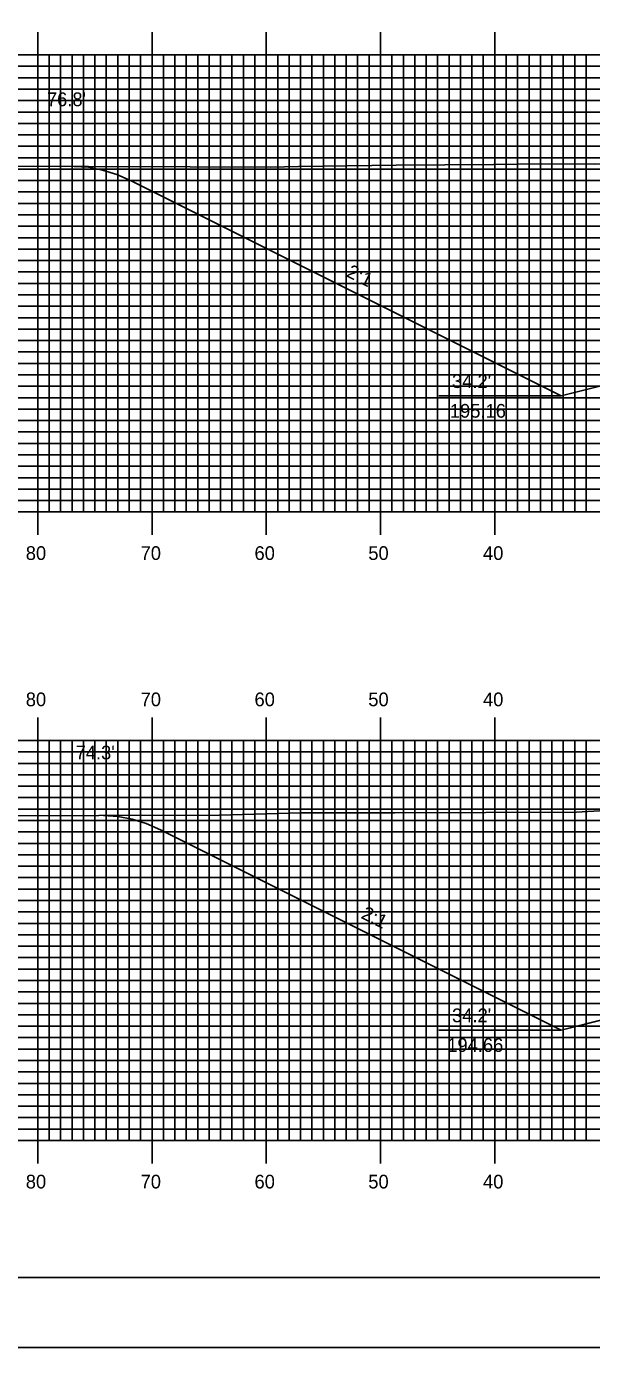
# Model space of a CAD drawing. Extents: x 1800355 to 1800699, y 442591 to 442811.
# Drawn here: x 1800440 to 1800489.5, y 442590.5 to 442706.2 of the extents above; entities that cross this region are included whole.
import ezdxf

# ---------------------------------------------------------------- set-up
doc = ezdxf.new("R2010")
doc.units = 0
for name, color, linetype in [('ANNOTATION', 7, 'Continuous'), ('BORDER', 7, 'Continuous'), ('D_Roadway_Centerline', 7, 'Continuous'), ('D_Roadway_SlopeLines', 7, 'Continuous'), ('D_Text_Standard', 7, 'Continuous'), ('H_V ANNOTATION', 7, 'Continuous'), ('MAJOR', 7, 'Continuous'), ('MINOR', 7, 'Continuous'), ('PDRAIN', 7, 'Continuous'), ('PLOT BOUNDARY', 7, 'Continuous'), ('S_Roadway_Centerline', 7, 'Continuous')]:
    doc.layers.add(name, color=color, linetype=linetype)

msp = doc.modelspace()

# ---------------------------------------------------------------- linework, layer by layer
at = {"layer": 'BORDER'}
msp.add_lwpolyline([(1800371.44, 442596.67), (1800691.44, 442596.67), (1800691.44, 442806.67), (1800371.44, 442806.67)], close=True, dxfattribs=at)
at = {"layer": 'D_Roadway_Centerline'}
msp.add_lwpolyline([(1800446.79, 442637.11), (1800448.04, 442637.03), (1800449.29, 442636.8), (1800450.54, 442636.41), (1800451.79, 442635.86), (1800486.86, 442618.33), (1800490.86, 442619.33), (1800501.04, 442621.87), (1800509.04, 442622.19), (1800521.04, 442621.95), (1800533.04, 442621.71), (1800541.04, 442621.39), (1800551.21, 442618.85), (1800555.21, 442617.85), (1800591.97, 442636.22), (1800593.22, 442636.77), (1800594.47, 442637.16), (1800595.72, 442637.38), (1800596.97, 442637.45)], dxfattribs=at)
at = {"layer": 'D_Roadway_SlopeLines'}
for points in [[(1800486.86, 442673.83), (1800449.22, 442692.65), (1800447.97, 442693.2), (1800446.72, 442693.59), (1800445.47, 442693.83), (1800444.22, 442693.91)], [(1800501.04, 442677.37), (1800486.86, 442673.83)], [(1800486.86, 442618.33), (1800451.79, 442635.86), (1800450.54, 442636.41), (1800449.29, 442636.8), (1800448.04, 442637.03), (1800446.79, 442637.11)], [(1800501.04, 442621.87), (1800486.86, 442618.33)]]:
    msp.add_lwpolyline(points, dxfattribs=at)
at = {"layer": 'MAJOR'}
for p, q in [((1800441.04, 442705.67), (1800441.04, 442703.67)), ((1800451.04, 442705.67), (1800451.04, 442703.67)), ((1800461.04, 442705.67), (1800461.04, 442703.67)), ((1800471.04, 442705.67), (1800471.04, 442703.67)), ((1800481.04, 442705.67), (1800481.04, 442703.67)), ((1800381.04, 442703.67), (1800661.04, 442703.67)), ((1800381.04, 442703.67), (1800661.04, 442703.67)), ((1800441.04, 442663.67), (1800441.04, 442703.67)), ((1800451.04, 442663.67), (1800451.04, 442703.67)), ((1800461.04, 442663.67), (1800461.04, 442703.67)), ((1800471.04, 442663.67), (1800471.04, 442703.67)), ((1800481.04, 442663.67), (1800481.04, 442703.67)), ((1800381.04, 442698.67), (1800661.04, 442698.67)), ((1800381.04, 442693.67), (1800661.04, 442693.67)), ((1800381.04, 442688.67), (1800661.04, 442688.67)), ((1800381.04, 442683.67), (1800661.04, 442683.67)), ((1800381.04, 442678.67), (1800661.04, 442678.67)), ((1800381.04, 442673.67), (1800661.04, 442673.67)), ((1800381.04, 442668.67), (1800661.04, 442668.67)), ((1800381.04, 442663.67), (1800661.04, 442663.67)), ((1800381.04, 442663.67), (1800661.04, 442663.67)), ((1800441.04, 442661.66), (1800441.04, 442663.67)), ((1800451.04, 442661.66), (1800451.04, 442663.67)), ((1800461.04, 442661.66), (1800461.04, 442663.67)), ((1800471.04, 442661.66), (1800471.04, 442663.67)), ((1800481.04, 442661.66), (1800481.04, 442663.67)), ((1800441.04, 442645.67), (1800441.04, 442643.67)), ((1800451.04, 442645.67), (1800451.04, 442643.67)), ((1800461.04, 442645.67), (1800461.04, 442643.67)), ((1800471.04, 442645.67), (1800471.04, 442643.67)), ((1800481.04, 442645.67), (1800481.04, 442643.67)), ((1800381.04, 442643.67), (1800661.04, 442643.67)), ((1800381.04, 442643.67), (1800661.04, 442643.67)), ((1800441.04, 442608.67), (1800441.04, 442643.67)), ((1800451.04, 442608.67), (1800451.04, 442643.67)), ((1800461.04, 442608.67), (1800461.04, 442643.67)), ((1800471.04, 442608.67), (1800471.04, 442643.67)), ((1800481.04, 442608.67), (1800481.04, 442643.67)), ((1800381.04, 442638.67), (1800661.04, 442638.67)), ((1800381.04, 442633.67), (1800661.04, 442633.67)), ((1800381.04, 442628.67), (1800661.04, 442628.67)), ((1800381.04, 442623.67), (1800661.04, 442623.67)), ((1800381.04, 442618.67), (1800661.04, 442618.67)), ((1800381.04, 442613.67), (1800661.04, 442613.67)), ((1800381.04, 442608.67), (1800661.04, 442608.67)), ((1800381.04, 442608.67), (1800661.04, 442608.67)), ((1800441.04, 442606.66), (1800441.04, 442608.67)), ((1800451.04, 442606.66), (1800451.04, 442608.67)), ((1800461.04, 442606.66), (1800461.04, 442608.67)), ((1800471.04, 442606.66), (1800471.04, 442608.67)), ((1800481.04, 442606.66), (1800481.04, 442608.67))]:
    msp.add_line(p, q, dxfattribs=at)
at = {"layer": 'MINOR'}
for p, q in [((1800442.04, 442663.67), (1800442.04, 442703.67)), ((1800443.04, 442663.67), (1800443.04, 442703.67)), ((1800444.04, 442663.67), (1800444.04, 442703.67)), ((1800445.04, 442663.67), (1800445.04, 442703.67)), ((1800446.04, 442663.67), (1800446.04, 442703.67)), ((1800447.04, 442663.67), (1800447.04, 442703.67)), ((1800448.04, 442663.67), (1800448.04, 442703.67)), ((1800449.04, 442663.67), (1800449.04, 442703.67)), ((1800450.04, 442663.67), (1800450.04, 442703.67)), ((1800452.04, 442663.67), (1800452.04, 442703.67)), ((1800453.04, 442663.67), (1800453.04, 442703.67)), ((1800454.04, 442663.67), (1800454.04, 442703.67)), ((1800455.04, 442663.67), (1800455.04, 442703.67)), ((1800456.04, 442663.67), (1800456.04, 442703.67)), ((1800457.04, 442663.67), (1800457.04, 442703.67)), ((1800458.04, 442663.67), (1800458.04, 442703.67)), ((1800459.04, 442663.67), (1800459.04, 442703.67)), ((1800460.04, 442663.67), (1800460.04, 442703.67)), ((1800462.04, 442663.67), (1800462.04, 442703.67)), ((1800463.04, 442663.67), (1800463.04, 442703.67)), ((1800464.04, 442663.67), (1800464.04, 442703.67)), ((1800465.04, 442663.67), (1800465.04, 442703.67)), ((1800466.04, 442663.67), (1800466.04, 442703.67)), ((1800467.04, 442663.67), (1800467.04, 442703.67)), ((1800468.04, 442663.67), (1800468.04, 442703.67)), ((1800469.04, 442663.67), (1800469.04, 442703.67)), ((1800470.04, 442663.67), (1800470.04, 442703.67)), ((1800472.04, 442663.67), (1800472.04, 442703.67)), ((1800473.04, 442663.67), (1800473.04, 442703.67)), ((1800474.04, 442663.67), (1800474.04, 442703.67)), ((1800475.04, 442663.67), (1800475.04, 442703.67)), ((1800476.04, 442663.67), (1800476.04, 442703.67)), ((1800477.04, 442663.67), (1800477.04, 442703.67)), ((1800478.04, 442663.67), (1800478.04, 442703.67)), ((1800479.04, 442663.67), (1800479.04, 442703.67)), ((1800480.04, 442663.67), (1800480.04, 442703.67)), ((1800482.04, 442663.67), (1800482.04, 442703.67)), ((1800483.04, 442663.67), (1800483.04, 442703.67)), ((1800484.04, 442663.67), (1800484.04, 442703.67)), ((1800485.04, 442663.67), (1800485.04, 442703.67)), ((1800486.04, 442663.67), (1800486.04, 442703.67)), ((1800487.04, 442663.67), (1800487.04, 442703.67)), ((1800488.04, 442663.67), (1800488.04, 442703.67)), ((1800489.04, 442663.67), (1800489.04, 442703.67)), ((1800381.04, 442702.67), (1800661.04, 442702.67)), ((1800381.04, 442701.67), (1800661.04, 442701.67)), ((1800381.04, 442700.67), (1800661.04, 442700.67)), ((1800381.04, 442699.67), (1800661.04, 442699.67)), ((1800381.04, 442697.67), (1800661.04, 442697.67)), ((1800381.04, 442696.67), (1800661.04, 442696.67)), ((1800381.04, 442695.67), (1800661.04, 442695.67)), ((1800381.04, 442694.67), (1800661.04, 442694.67)), ((1800381.04, 442692.67), (1800661.04, 442692.67)), ((1800381.04, 442691.67), (1800661.04, 442691.67)), ((1800381.04, 442690.67), (1800661.04, 442690.67)), ((1800381.04, 442689.67), (1800661.04, 442689.67)), ((1800381.04, 442687.67), (1800661.04, 442687.67)), ((1800381.04, 442686.67), (1800661.04, 442686.67)), ((1800381.04, 442685.67), (1800661.04, 442685.67)), ((1800381.04, 442684.67), (1800661.04, 442684.67)), ((1800381.04, 442682.67), (1800661.04, 442682.67)), ((1800381.04, 442681.67), (1800661.04, 442681.67)), ((1800381.04, 442680.67), (1800661.04, 442680.67)), ((1800381.04, 442679.67), (1800661.04, 442679.67)), ((1800381.04, 442677.67), (1800661.04, 442677.67)), ((1800381.04, 442676.67), (1800661.04, 442676.67)), ((1800381.04, 442675.67), (1800661.04, 442675.67)), ((1800381.04, 442674.67), (1800661.04, 442674.67)), ((1800381.04, 442672.67), (1800661.04, 442672.67)), ((1800381.04, 442671.67), (1800661.04, 442671.67)), ((1800381.04, 442670.67), (1800661.04, 442670.67)), ((1800381.04, 442669.67), (1800661.04, 442669.67)), ((1800381.04, 442667.67), (1800661.04, 442667.67)), ((1800381.04, 442666.67), (1800661.04, 442666.67)), ((1800381.04, 442665.67), (1800661.04, 442665.67)), ((1800381.04, 442664.67), (1800661.04, 442664.67)), ((1800442.04, 442608.67), (1800442.04, 442643.67)), ((1800443.04, 442608.67), (1800443.04, 442643.67)), ((1800444.04, 442608.67), (1800444.04, 442643.67)), ((1800445.04, 442608.67), (1800445.04, 442643.67)), ((1800446.04, 442608.67), (1800446.04, 442643.67)), ((1800447.04, 442608.67), (1800447.04, 442643.67)), ((1800448.04, 442608.67), (1800448.04, 442643.67)), ((1800449.04, 442608.67), (1800449.04, 442643.67)), ((1800450.04, 442608.67), (1800450.04, 442643.67)), ((1800452.04, 442608.67), (1800452.04, 442643.67)), ((1800453.04, 442608.67), (1800453.04, 442643.67)), ((1800454.04, 442608.67), (1800454.04, 442643.67)), ((1800455.04, 442608.67), (1800455.04, 442643.67)), ((1800456.04, 442608.67), (1800456.04, 442643.67)), ((1800457.04, 442608.67), (1800457.04, 442643.67)), ((1800458.04, 442608.67), (1800458.04, 442643.67)), ((1800459.04, 442608.67), (1800459.04, 442643.67)), ((1800460.04, 442608.67), (1800460.04, 442643.67)), ((1800462.04, 442608.67), (1800462.04, 442643.67)), ((1800463.04, 442608.67), (1800463.04, 442643.67)), ((1800464.04, 442608.67), (1800464.04, 442643.67)), ((1800465.04, 442608.67), (1800465.04, 442643.67)), ((1800466.04, 442608.67), (1800466.04, 442643.67)), ((1800467.04, 442608.67), (1800467.04, 442643.67)), ((1800468.04, 442608.67), (1800468.04, 442643.67)), ((1800469.04, 442608.67), (1800469.04, 442643.67)), ((1800470.04, 442608.67), (1800470.04, 442643.67)), ((1800472.04, 442608.67), (1800472.04, 442643.67)), ((1800473.04, 442608.67), (1800473.04, 442643.67)), ((1800474.04, 442608.67), (1800474.04, 442643.67)), ((1800475.04, 442608.67), (1800475.04, 442643.67)), ((1800476.04, 442608.67), (1800476.04, 442643.67)), ((1800477.04, 442608.67), (1800477.04, 442643.67)), ((1800478.04, 442608.67), (1800478.04, 442643.67)), ((1800479.04, 442608.67), (1800479.04, 442643.67)), ((1800480.04, 442608.67), (1800480.04, 442643.67)), ((1800482.04, 442608.67), (1800482.04, 442643.67)), ((1800483.04, 442608.67), (1800483.04, 442643.67)), ((1800484.04, 442608.67), (1800484.04, 442643.67)), ((1800485.04, 442608.67), (1800485.04, 442643.67)), ((1800486.04, 442608.67), (1800486.04, 442643.67)), ((1800487.04, 442608.67), (1800487.04, 442643.67)), ((1800488.04, 442608.67), (1800488.04, 442643.67)), ((1800489.04, 442608.67), (1800489.04, 442643.67)), ((1800381.04, 442642.67), (1800661.04, 442642.67)), ((1800381.04, 442641.67), (1800661.04, 442641.67)), ((1800381.04, 442640.67), (1800661.04, 442640.67)), ((1800381.04, 442639.67), (1800661.04, 442639.67)), ((1800381.04, 442637.67), (1800661.04, 442637.67)), ((1800381.04, 442636.67), (1800661.04, 442636.67)), ((1800381.04, 442635.67), (1800661.04, 442635.67)), ((1800381.04, 442634.67), (1800661.04, 442634.67)), ((1800381.04, 442632.67), (1800661.04, 442632.67)), ((1800381.04, 442631.67), (1800661.04, 442631.67)), ((1800381.04, 442630.67), (1800661.04, 442630.67)), ((1800381.04, 442629.67), (1800661.04, 442629.67)), ((1800381.04, 442627.67), (1800661.04, 442627.67)), ((1800381.04, 442626.67), (1800661.04, 442626.67)), ((1800381.04, 442625.67), (1800661.04, 442625.67)), ((1800381.04, 442624.67), (1800661.04, 442624.67)), ((1800381.04, 442622.67), (1800661.04, 442622.67)), ((1800381.04, 442621.67), (1800661.04, 442621.67)), ((1800381.04, 442620.67), (1800661.04, 442620.67)), ((1800381.04, 442619.67), (1800661.04, 442619.67)), ((1800381.04, 442617.67), (1800661.04, 442617.67)), ((1800381.04, 442616.67), (1800661.04, 442616.67)), ((1800381.04, 442615.67), (1800661.04, 442615.67)), ((1800381.04, 442614.67), (1800661.04, 442614.67)), ((1800381.04, 442612.67), (1800661.04, 442612.67)), ((1800381.04, 442611.67), (1800661.04, 442611.67)), ((1800381.04, 442610.67), (1800661.04, 442610.67)), ((1800381.04, 442609.67), (1800661.04, 442609.67))]:
    msp.add_line(p, q, dxfattribs=at)
at = {"layer": 'PDRAIN'}
for p, q in [((1800476.14, 442673.83), (1800486.86, 442673.83)), ((1800476.14, 442618.33), (1800486.86, 442618.33))]:
    msp.add_line(p, q, dxfattribs=at)
at = {"layer": 'PLOT BOUNDARY'}
msp.add_lwpolyline([(1800355.25, 442590.55), (1800695.25, 442590.55), (1800695.25, 442810.55), (1800355.25, 442810.55)], close=True, dxfattribs=at)
at = {"layer": 'S_Roadway_Centerline'}
for points in [[(1800436.57, 442693.94), (1800454.39, 442693.87), (1800461.41, 442693.85), (1800463.87, 442693.89), (1800472.4, 442694.01), (1800480.94, 442694.09), (1800485.15, 442694.12), (1800489.76, 442694.1), (1800496.49, 442694.17), (1800502.17, 442694.09), (1800507.43, 442694.11), (1800513.66, 442693.96), (1800520.43, 442693.96), (1800524.83, 442694.18), (1800538.54, 442694.14), (1800542.86, 442693.92), (1800546.46, 442693.82), (1800564.02, 442693.97), (1800566.6, 442694.05), (1800568.72, 442694.12), (1800587.56, 442694.01)], [(1800381.04, 442637.58), (1800384.71, 442637.57), (1800390.59, 442637.59), (1800394.62, 442637.58), (1800399.16, 442637.61), (1800413.83, 442637.41), (1800418.38, 442637.2), (1800435.83, 442637.08), (1800456.92, 442637.13), (1800464, 442637.33), (1800472.3, 442637.35), (1800488.2, 442637.4), (1800495.71, 442637.84), (1800501.91, 442637.88), (1800511.04, 442637.36), (1800520.11, 442637.45), (1800523.46, 442637.46), (1800533.83, 442637.49), (1800544.8, 442637.36), (1800557.05, 442637.45), (1800568.72, 442637.52), (1800571.52, 442637.59), (1800590.67, 442637.52)]]:
    msp.add_lwpolyline(points, dxfattribs=at)

# ---------------------------------------------------------------- texts
at = {"layer": 'ANNOTATION'}
for p in [(1800467.97, 442684.31), (1800469.26, 442628.16)]:
    msp.add_text('2:1', height=1.2, rotation=333.4349, dxfattribs=at).set_placement(p)
for s, p in [("34.2'", (1800477.3, 442674.52)), ('195.16', (1800477.11, 442671.92)), ("34.2'", (1800477.3, 442619.02)), ('194.66', (1800476.88, 442616.42))]:
    msp.add_text(s, height=1.2, dxfattribs=at).set_placement(p)
at = {"layer": 'D_Text_Standard'}
for s, p in [("76.8'", (1800441.84, 442699.18)), ("74.3'", (1800444.35, 442642.02))]:
    msp.add_text(s, height=1.2, dxfattribs=at).set_placement(p)
at = {"layer": 'H_V ANNOTATION'}
for s, p in [('80', (1800439.99, 442659.47)), ('70', (1800450.04, 442659.47)), ('60', (1800460.01, 442659.47)), ('50', (1800469.97, 442659.47)), ('40', (1800480.01, 442659.47)), ('80', (1800439.99, 442646.67)), ('70', (1800450.04, 442646.67)), ('60', (1800460.01, 442646.67)), ('50', (1800469.97, 442646.67)), ('40', (1800480.01, 442646.67)), ('80', (1800439.99, 442604.47)), ('70', (1800450.04, 442604.47)), ('60', (1800460.01, 442604.47)), ('50', (1800469.97, 442604.47)), ('40', (1800480.01, 442604.47))]:
    msp.add_text(s, height=1.2, dxfattribs=at).set_placement(p)

doc.saveas('drawing.dxf')
